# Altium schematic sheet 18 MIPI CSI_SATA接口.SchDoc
size 420 x 297 mm
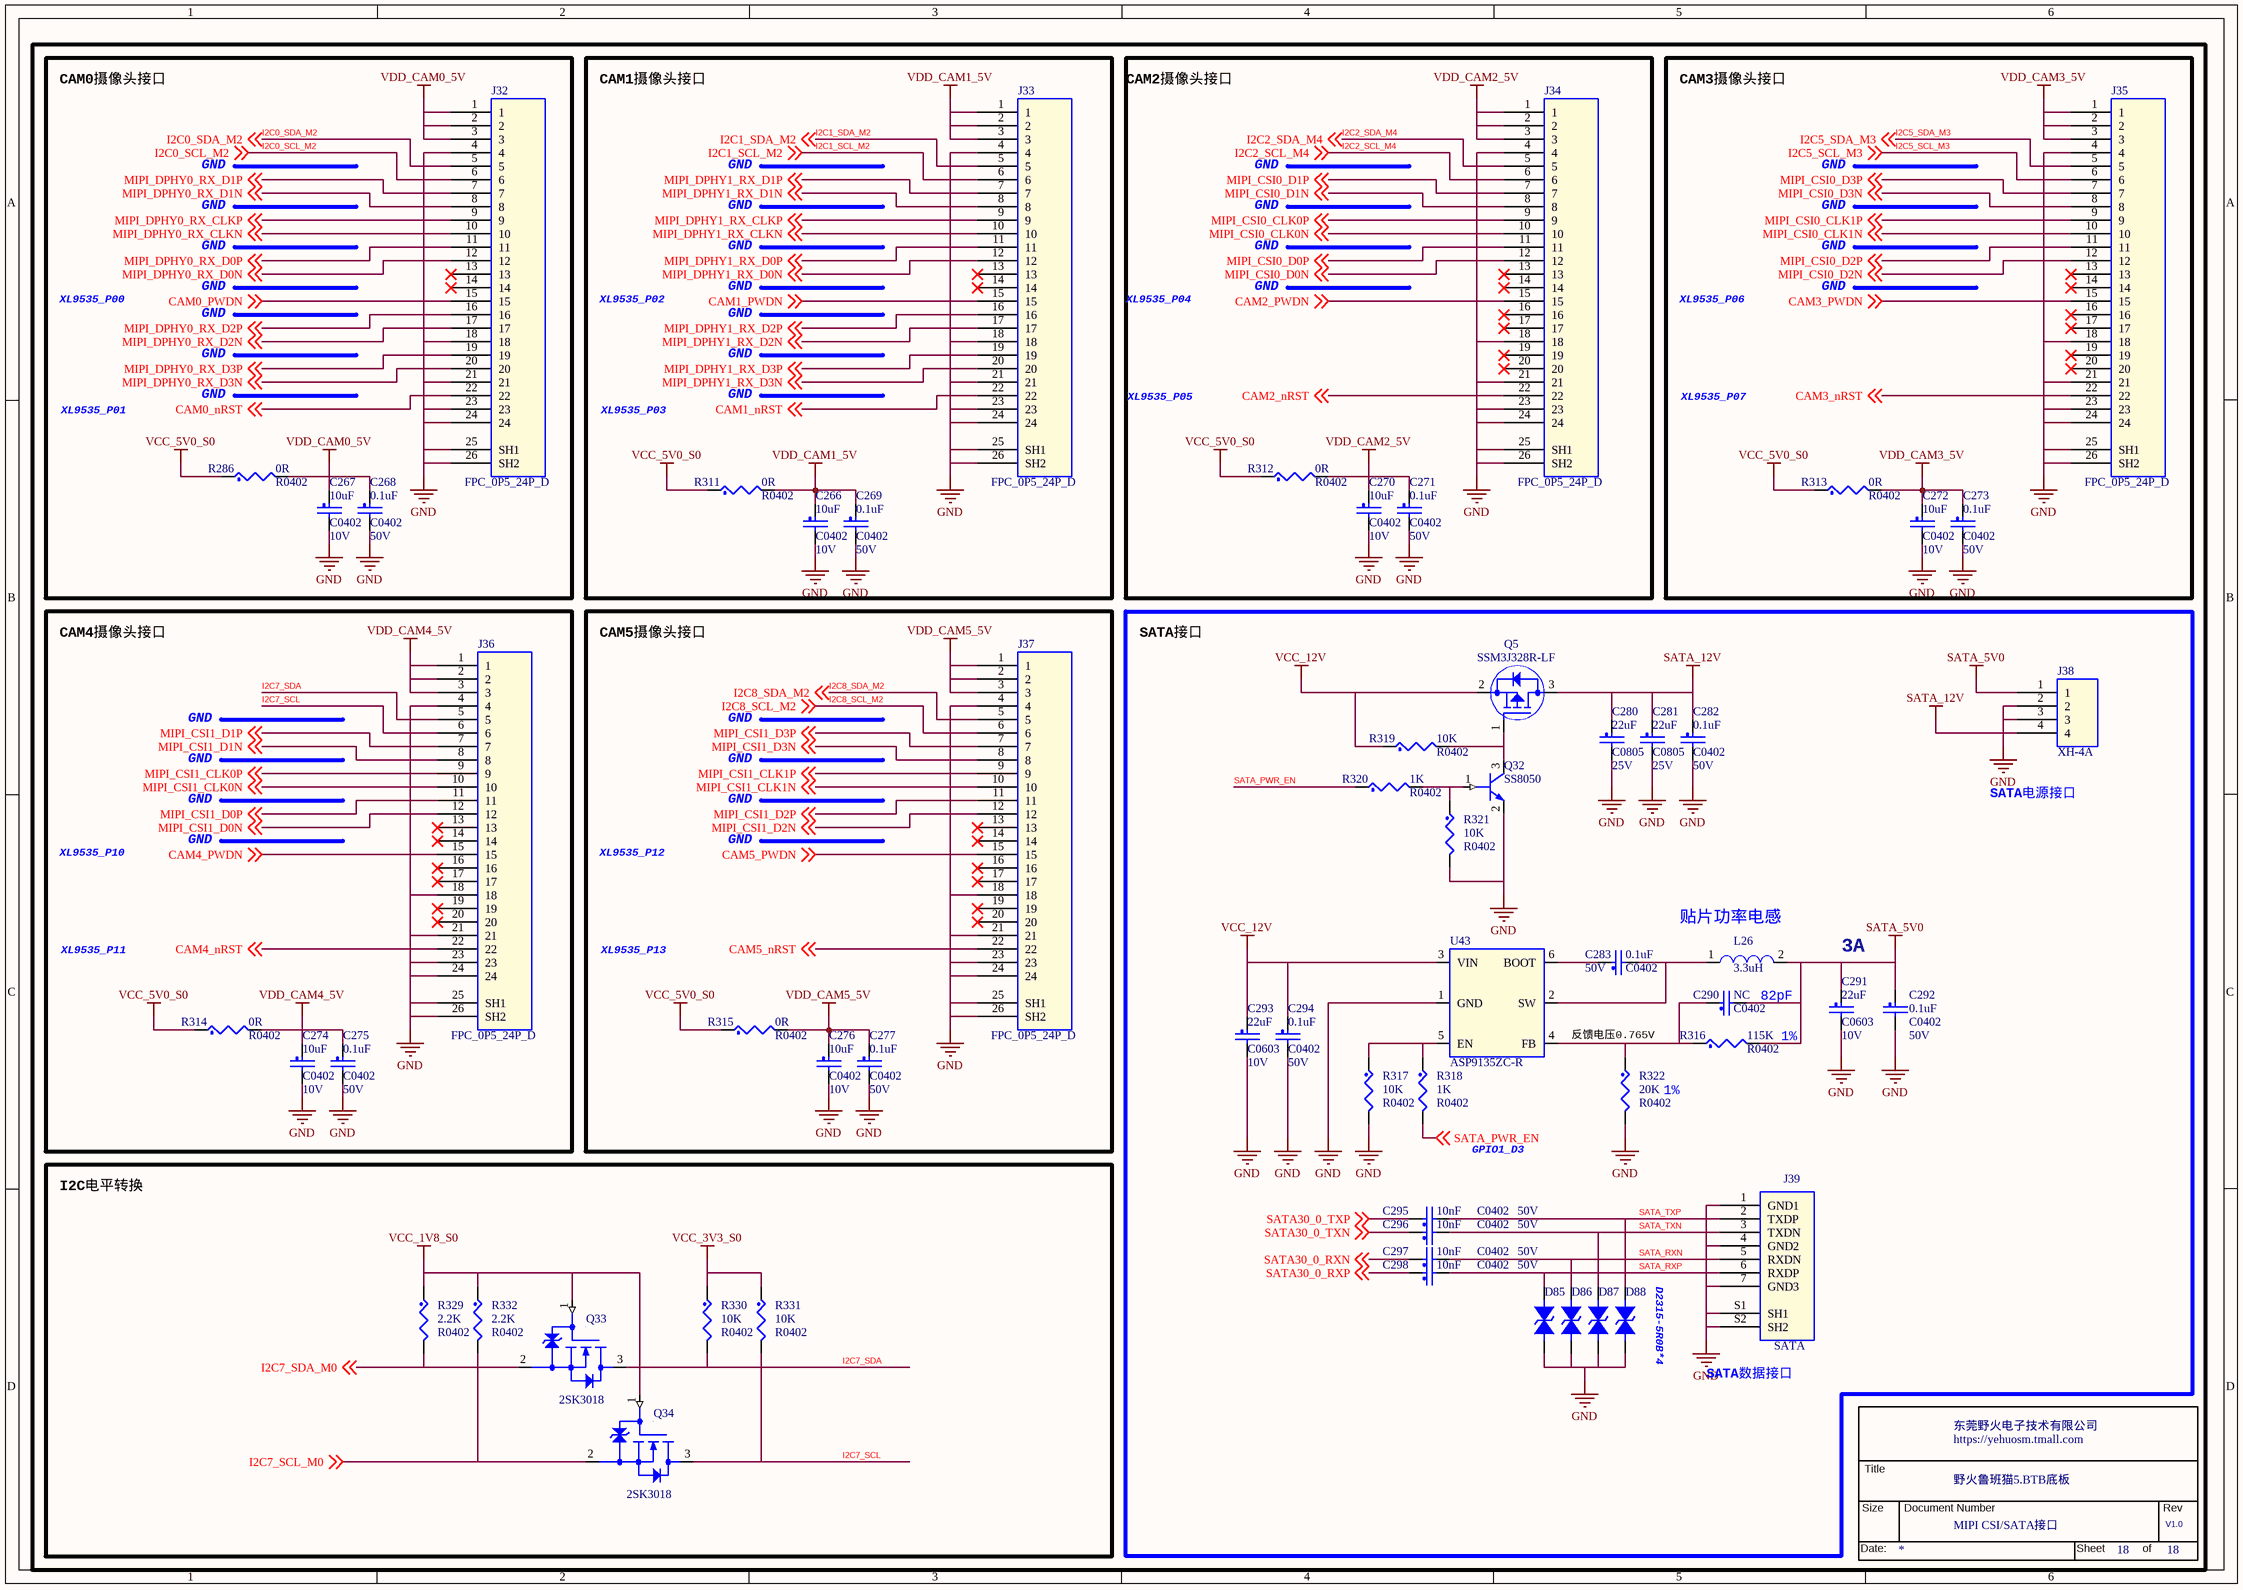
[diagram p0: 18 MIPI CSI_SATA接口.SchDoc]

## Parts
*  Doc: MIPI CSI/SATA接口  RevCode: V1.0  Title: 野火鲁班猫5.BTB底板  OrgName: 东莞野火电子技术有限公司  Page Number: 18  (hidden comment: TitleBlock_YHSCH)  (graphical)
C266  10uF  Voltage: 10V  [C0402]
C267  10uF  Voltage: 10V  [C0402]
C268  0.1uF  Voltage: 50V  [C0402]
C269  0.1uF  Voltage: 50V  [C0402]
C270  10uF  Voltage: 10V  [C0402]
C271  0.1uF  Voltage: 50V  [C0402]
C272  10uF  Voltage: 10V  [C0402]
C273  0.1uF  Voltage: 50V  [C0402]
C274  10uF  Voltage: 10V  [C0402]
C275  0.1uF  Voltage: 50V  [C0402]
C276  10uF  Voltage: 10V  [C0402]
C277  0.1uF  Voltage: 50V  [C0402]
C280  22uF  Voltage: 25V  [C0805]
C281  22uF  Voltage: 25V  [C0805]
C282  0.1uF  Voltage: 50V  [C0402]
C283  0.1uF  Voltage: 50V  [C0402]
C290  NC  [C0402]
C291  22uF  Voltage: 10V  [C0603]
C292  0.1uF  Voltage: 50V  [C0402]
C293  22uF  Voltage: 10V  [C0603]
C294  0.1uF  Voltage: 50V  [C0402]
C295  10nF  Voltage: 50V  [C0402]
C296  10nF  Voltage: 50V  [C0402]
C297  10nF  Voltage: 50V  [C0402]
C298  10nF  Voltage: 50V  [C0402]
D85  D2315-5R0B  [D0603/SMD]  (value not drawn)
D86  D2315-5R0B  [D0603/SMD]  (value not drawn)
D87  D2315-5R0B  [D0603/SMD]  (value not drawn)
D88  D2315-5R0B  [D0603/SMD]  (value not drawn)
J32  FPC_0P5_24P_D  [fpc_24p_0p5]
J33  FPC_0P5_24P_D  [fpc_24p_0p5]
J34  FPC_0P5_24P_D  [fpc_24p_0p5]
J35  FPC_0P5_24P_D  [fpc_24p_0p5]
J36  FPC_0P5_24P_D  [fpc_24p_0p5]
J37  FPC_0P5_24P_D  [fpc_24p_0p5]
J38  XH-4A  [XH2p54-4p]
J39  SATA  [ssata_v]
L26  3.3uH  [l4520]
Q5  SSM3J328R-LF  [SOT23]
Q32  SS8050  [SOT23]
Q33  2SK3018  [SOT23]
Q34  2SK3018  [SOT23]
R286  0R  [R0402]
R311  0R  [R0402]
R312  0R  [R0402]
R313  0R  [R0402]
R314  0R  [R0402]
R315  0R  [R0402]
R316  115K  [R0402]
R317  10K  [R0402]
R318  1K  [R0402]
R319  10K  [R0402]
R320  1K  [R0402]
R321  10K  [R0402]
R322  20K  [R0402]
R329  2.2K  [R0402]
R330  10K  [R0402]
R331  10K  [R0402]
R332  2.2K  [R0402]
U43  ASP9135ZC-R  [SOT23_6]

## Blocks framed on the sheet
CAM0摄像头接口: C267 C268 J32 R286
CAM1摄像头接口: C266 C269 J33 R311
CAM2摄像头接口: C270 C271 J34 R312
CAM3摄像头接口: C272 C273 J35 R313
CAM4摄像头接口: C274 C275 J36 R314
CAM5摄像头接口: C276 C277 J37 R315
3A: C280-C283 C290-C298 D85-D88 J38 J39 L26 Q5 Q32 R316-R322 U43
I2C电平转换: Q33 Q34 R329-R332

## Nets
GND: C266.2 C267.2 C268.2 C269.2 C270.2 C271.2 C272.2 C273.2 C274.2 C275.2 C276.2 C277.2 C280.2 C281.2 C282.2 C291.2 C292.2 C293.2 C294.2 D85.1 D86.1 D87.1 D88.1 J32.4 J32.18 J32.21 J32.23 J32.24 J32.25(SH1) J32.26(SH2) J33.4 J33.18 J33.21 J33.23 J33.24 J33.25(SH1) J33.26(SH2) J34.4 J34.18 J34.21 J34.23 J34.24 J34.25(SH1) J34.26(SH2) J35.4 J35.18 J35.21 J35.23 J35.24 J35.25(SH1) J35.26(SH2) J36.4 J36.18 J36.21 J36.23 J36.24 J36.25(SH1) J36.26(SH2) J37.4 J37.18 J37.21 J37.23 J37.24 J37.25(SH1) J37.26(SH2) J38.2 J38.3 J39.1(GND1) J39.4(GND2) J39.7(GND3) J39.S1(SH1) J39.S2(SH2) Q32.2(EMITTER) R317.2 R321.2 R322.2 U43.1(GND)
SATA_5V0: C290.2 C291.1 C292.1 J38.1 L26.2 R316.2
SATA_12V: C280.1 C281.1 C282.1 J38.4 Q5.3(DRAIN)
VCC_1V8_S0: Q33.1(GATE) Q34.1(GATE) R329.1 R332.1
VCC_3V3_S0: R330.1 R331.1
VCC_5V0_S0: R286.1 R311.1 R312.1 R313.1 R314.1 R315.1
VCC_12V: C293.1 C294.1 Q5.2(SOURCE) R319.1 U43.3(VIN)
VDD_CAM0_5V: C267.1 C268.1 J32.1 J32.2 J32.3 R286.2
VDD_CAM1_5V: C266.1 C269.1 J33.1 J33.2 J33.3 R311.2
VDD_CAM2_5V: C270.1 C271.1 J34.1 J34.2 J34.3 R312.2
VDD_CAM3_5V: C272.1 C273.1 J35.1 J35.2 J35.3 R313.2
VDD_CAM4_5V: C274.1 C275.1 J36.1 J36.2 J36.3 R314.2
VDD_CAM5_5V: C276.1 C277.1 J37.1 J37.2 J37.3 R315.2
CAM0_nRST: J32.22 ; off-sheet CAM0_nRST
CAM0_PWDN: J32.15 ; off-sheet CAM0_PWDN
CAM1_nRST: J33.22 ; off-sheet CAM1_nRST
CAM1_PWDN: J33.15 ; off-sheet CAM1_PWDN
CAM2_nRST: J34.22 ; off-sheet CAM2_nRST
CAM2_PWDN: J34.15 ; off-sheet CAM2_PWDN
CAM3_nRST: J35.22 ; off-sheet CAM3_nRST
CAM3_PWDN: J35.15 ; off-sheet CAM3_PWDN
CAM4_nRST: J36.22 ; off-sheet CAM4_nRST
CAM4_PWDN: J36.15 ; off-sheet CAM4_PWDN
CAM5_nRST: J37.22 ; off-sheet CAM5_nRST
CAM5_PWDN: J37.15 ; off-sheet CAM5_PWDN
I2C0_SCL_M2: J32.6 ; off-sheet I2C0_SCL_M2
I2C0_SDA_M2: J32.5 ; off-sheet I2C0_SDA_M2
I2C1_SCL_M2: J33.6 ; off-sheet I2C1_SCL_M2
I2C1_SDA_M2: J33.5 ; off-sheet I2C1_SDA_M2
I2C2_SCL_M4: J34.6 ; off-sheet I2C2_SCL_M4
I2C2_SDA_M4: J34.5 ; off-sheet I2C2_SDA_M4
I2C5_SCL_M3: J35.6 ; off-sheet I2C5_SCL_M3
I2C5_SDA_M3: J35.5 ; off-sheet I2C5_SDA_M3
I2C7_SCL: J36.6 Q34.3(DRAIN) R331.2
I2C7_SCL_M0: Q34.2(SOURCE) R332.2 ; off-sheet I2C7_SCL_M0
I2C7_SDA: J36.5 Q33.3(DRAIN) R330.2
I2C7_SDA_M0: Q33.2(SOURCE) R329.2 ; off-sheet I2C7_SDA_M0
I2C8_SCL_M2: J37.6 ; off-sheet I2C8_SCL_M2
I2C8_SDA_M2: J37.5 ; off-sheet I2C8_SDA_M2
MIPI_CSI0_CLK0N: J34.10 ; off-sheet MIPI_CSI0_CLK0N
MIPI_CSI0_CLK0P: J34.9 ; off-sheet MIPI_CSI0_CLK0P
MIPI_CSI0_CLK1N: J35.10 ; off-sheet MIPI_CSI0_CLK1N
MIPI_CSI0_CLK1P: J35.9 ; off-sheet MIPI_CSI0_CLK1P
MIPI_CSI0_D0N: J34.12 ; off-sheet MIPI_CSI0_D0N
MIPI_CSI0_D0P: J34.11 ; off-sheet MIPI_CSI0_D0P
MIPI_CSI0_D1N: J34.8 ; off-sheet MIPI_CSI0_D1N
MIPI_CSI0_D1P: J34.7 ; off-sheet MIPI_CSI0_D1P
MIPI_CSI0_D2N: J35.12 ; off-sheet MIPI_CSI0_D2N
MIPI_CSI0_D2P: J35.11 ; off-sheet MIPI_CSI0_D2P
MIPI_CSI0_D3N: J35.8 ; off-sheet MIPI_CSI0_D3N
MIPI_CSI0_D3P: J35.7 ; off-sheet MIPI_CSI0_D3P
MIPI_CSI1_CLK0N: J36.10 ; off-sheet MIPI_CSI1_CLK0N
MIPI_CSI1_CLK0P: J36.9 ; off-sheet MIPI_CSI1_CLK0P
MIPI_CSI1_CLK1N: J37.10 ; off-sheet MIPI_CSI1_CLK1N
MIPI_CSI1_CLK1P: J37.9 ; off-sheet MIPI_CSI1_CLK1P
MIPI_CSI1_D0N: J36.12 ; off-sheet MIPI_CSI1_D0N
MIPI_CSI1_D0P: J36.11 ; off-sheet MIPI_CSI1_D0P
MIPI_CSI1_D1N: J36.8 ; off-sheet MIPI_CSI1_D1N
MIPI_CSI1_D1P: J36.7 ; off-sheet MIPI_CSI1_D1P
MIPI_CSI1_D2N: J37.12 ; off-sheet MIPI_CSI1_D2N
MIPI_CSI1_D2P: J37.11 ; off-sheet MIPI_CSI1_D2P
MIPI_CSI1_D3N: J37.8 ; off-sheet MIPI_CSI1_D3N
MIPI_CSI1_D3P: J37.7 ; off-sheet MIPI_CSI1_D3P
MIPI_DPHY0_RX_CLKN: J32.10 ; off-sheet MIPI_DPHY0_RX_CLKN
MIPI_DPHY0_RX_CLKP: J32.9 ; off-sheet MIPI_DPHY0_RX_CLKP
MIPI_DPHY0_RX_D0N: J32.12 ; off-sheet MIPI_DPHY0_RX_D0N
MIPI_DPHY0_RX_D0P: J32.11 ; off-sheet MIPI_DPHY0_RX_D0P
MIPI_DPHY0_RX_D1N: J32.8 ; off-sheet MIPI_DPHY0_RX_D1N
MIPI_DPHY0_RX_D1P: J32.7 ; off-sheet MIPI_DPHY0_RX_D1P
MIPI_DPHY0_RX_D2N: J32.17 ; off-sheet MIPI_DPHY0_RX_D2N
MIPI_DPHY0_RX_D2P: J32.16 ; off-sheet MIPI_DPHY0_RX_D2P
MIPI_DPHY0_RX_D3N: J32.20 ; off-sheet MIPI_DPHY0_RX_D3N
MIPI_DPHY0_RX_D3P: J32.19 ; off-sheet MIPI_DPHY0_RX_D3P
MIPI_DPHY1_RX_CLKN: J33.10 ; off-sheet MIPI_DPHY1_RX_CLKN
MIPI_DPHY1_RX_CLKP: J33.9 ; off-sheet MIPI_DPHY1_RX_CLKP
MIPI_DPHY1_RX_D0N: J33.12 ; off-sheet MIPI_DPHY1_RX_D0N
MIPI_DPHY1_RX_D0P: J33.11 ; off-sheet MIPI_DPHY1_RX_D0P
MIPI_DPHY1_RX_D1N: J33.8 ; off-sheet MIPI_DPHY1_RX_D1N
MIPI_DPHY1_RX_D1P: J33.7 ; off-sheet MIPI_DPHY1_RX_D1P
MIPI_DPHY1_RX_D2N: J33.17 ; off-sheet MIPI_DPHY1_RX_D2N
MIPI_DPHY1_RX_D2P: J33.16 ; off-sheet MIPI_DPHY1_RX_D2P
MIPI_DPHY1_RX_D3N: J33.20 ; off-sheet MIPI_DPHY1_RX_D3N
MIPI_DPHY1_RX_D3P: J33.19 ; off-sheet MIPI_DPHY1_RX_D3P
SATA30_0_RXN: C297.1 ; off-sheet SATA30_0_RXN
SATA30_0_RXP: C298.1 ; off-sheet SATA30_0_RXP
SATA30_0_TXN: C296.1 ; off-sheet SATA30_0_TXN
SATA30_0_TXP: C295.1 ; off-sheet SATA30_0_TXP
SATA_PWR_EN: R318.2 R320.1 ; off-sheet SATA_PWR_EN
SATA_RXN: C297.2 D86.2 J39.5(RXDN)
SATA_RXP: C298.2 D85.2 J39.6(RXDP)
SATA_TXN: C296.2 D87.2 J39.3(TXDN)
SATA_TXP: C295.2 D88.2 J39.2(TXDP)
NetC283_1: C283.1 U43.6(BOOT)
NetC283_2: C283.2 L26.1 U43.2(SW)
NetC290_1: C290.1 R316.1 R322.1 U43.4(FB)
NetQ5_1: Q5.1(GATE) Q32.3(COLLECTOR) R319.2
NetQ32_1: Q32.1(BASE) R320.2 R321.1
NetR317_1: R317.1 R318.1 U43.5(EN)

Not connected (* = marked no-connect by the designer): J32 13* 14*; J33 13* 14*; J34 13* 14* 16* 17* 19* 20*; J35 13* 14* 16* 17* 19* 20*; J36 13* 14* 16* 17* 19* 20*; J37 13* 14* 16* 17* 19* 20*

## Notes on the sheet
- GND
- XL9535_P00
- XL9535_P02
- XL9535_P04
- XL9535_P06
- XL9535_P01
- XL9535_P03
- XL9535_P05
- XL9535_P07
- SATA接口
- SATA电源接口
- XL9535_P10
- XL9535_P12
- (near L26) 贴片功率电感
- XL9535_P11
- XL9535_P13
- 82pF
- 反馈电压0.765V
- 1%
- GPIO1_D3
- (near D88) D2315-5R0B*4
- (near J39) SATA数据接口

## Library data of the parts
* = TitleBlock_YHSCH: Cage Code: 1
C266 C267 = CAP_NP: CLASS: DISCRETE; 规格: 贴片电容10uF 20% 10V X5R 0402; 规格编号: CL05A106MP8NUB8; 条码: EBF29060247; 品牌: 三星; 类别: 贴片电容0402; 规格书: 三星电容.pdf; 价格: 0.518415; 生命周期: 量产
C268 C269 C282 C283 = CAP_NP: CLASS: DISCRETE; 生命周期: 量产; 价格: 0.029826; 规格书: 风华电容.pdf; 类别: 贴片电容0402; 品牌: 风华; 条码: EBF29060118; 规格编号: 0402X104K500NT; 规格: 贴片电容0.1uF 10% 50V X5R 0402
C270 C272 C274 C276 = CAP_NP: CLASS: DISCRETE; 生命周期: 量产; 价格: 0.518415; 规格书: 三星电容.pdf; 类别: 贴片电容0402; 品牌: 三星; 条码: EBF29060247; 规格编号: CL05A106MP8NUB8; 规格: 贴片电容10uF 20% 10V X5R 0402
C271 C273 C275 C277 C292 C294 = CAP_NP: CLASS: DISCRETE; 规格: 贴片电容0.1uF 10% 50V X5R 0402; 规格编号: 0402X104K500NT; 条码: EBF29060118; 品牌: 风华; 类别: 贴片电容0402; 规格书: 风华电容.pdf; 价格: 0.029826; 生命周期: 量产
C280 C281 = CAP_NP: CLASS: DISCRETE; 规格: 贴片电容22uF 20% 25V X5R 0805; 规格编号: 0805X226M250NT; 条码: EBF29060173; 品牌: 风华; 类别: 贴片电容0805; 规格书: 风华电容.pdf; 价格: 0.285631; 生命周期: 量产
C290 = CAP_NP: CLASS: DISCRETE; 规格: 贴片电容NC 预留; 条码: EBF29060149; 类别: 贴片电容0402
C291 C293 = CAP_NP: CLASS: DISCRETE; 生命周期: 量产; 价格: 0.078818; 规格书: 三星电容.pdf; 类别: 贴片电容0603; 品牌: 三星; 条码: EBF29060163; 规格编号: CL10A226MP8NUNE; 规格: 贴片电容22uF 20% 10V X5R 0603
C295-C298 = CAP_NP: CLASS: DISCRETE; 规格: 贴片电容10nF 10% 50V X7R 0402; 规格编号: CC0402KRX7R9BB103; 条码: EBF29060245; 品牌: 国巨; 类别: 贴片电容0402; 规格书: 国巨-贴片电容.pdf; 价格: 0.003808; 生命周期: 量产
D85-D88 = DIODE BI-DIR TRIG: PCB Footprint: esd0402; 备注: 通用; 生命周期: 量产; 规格书: 千虹_D2315-5R0B.pdf; 类别: 贴片ESD; 品牌: 千虹; 条码: EBFCIS240517170922; 规格: 防静电保护ESD二极管 反向工作电压5V 击穿电压7V 钳位电压10.5V 结电容Cj 0.3pF
J32-J36 = FPC-24P: 规格: FPC连接器 针脚数24 间距0.5mmm 下接 卧贴 翻盖式; 规格编号: AFC01-S24FCA-00; 条码: EBF29040059; 品牌: 钜硕电子; 类别: FPC连接器; 规格书: 钜硕电子-FPC间距0.5mm.pdf; 价格: 0.368739; 生命周期: 量产
J37 = FPC-24P: 可替代料: EBF29040059; 生命周期: 量产; 价格: 0.368739; 规格书: 钜硕电子-FPC间距0.5mm.pdf; 类别: FPC连接器; 品牌: 钜硕电子; 规格编号: AFC01-S24FCA-00; 规格: FPC连接器 针脚数24 间距0.5mmm 下接 卧贴 翻盖式
J38 = 1X4PIN: 可替代料: EBF29040012; 生命周期: 量产; 价格: 0.041116; 规格书: 博穆精密-XH2.54.pdf; 类别: XH连接器; 品牌: 博穆精密; 规格: 直针XH2.54-4P 间距2.54MM 拔插式 接插件 直插
J39 = SATA: 生命周期: 量产; 规格书: SATA_7PIN.pdf; 类别: SATA连接器; 品牌: 华宇创; 条码: EBF29040076; 规格编号: HYCW01-SATA07-205B; 规格: SATA 7PIN 全包开窗 A型
L26 = IND: CLASS: DISCRETE; 规格: 贴片电感3.3uH ±20% 3A 直流电阻69mΩ; 条码: EBF29050040; 品牌: 台庆; 类别: 贴片电感0402; 规格书: 台庆-功率电感.pdf; 生命周期: 量产; 规格编号: TMPC0402HP-3R3MG-Z02; 价格: 1.5992
Q5 = MOSFET_P: CLASS: IC; 丝印: KFH-XXX; 生命周期: 量产; 价格: 0.447836; 规格书: SSM3J328R-LF.pdf; 类别: P-MOS; 品牌: 东芝; 条码: EBF29280008; 规格编号: SSM3J328R LF; 规格: P沟道MOS 导通电阻29.8mΩ 电流3A 1.5V可驱动
Q32 = NPN: CLASS: IC; 丝印: Y1; 生命周期: 量产; 价格: 0.086744; 规格书: 江苏长电-SS8050Y1.pdf; 类别: 贴片三极管SOT-23; 品牌: 江苏长电; 条码: EBF29090001; 规格: 贴片三极管SS8050 集电极电流1.5A 额定功率300mW NPN
Q33 = 2SK3018: CLASS: IC; 丝印: KN; 生命周期: 量产; 价格: 0.120725; 规格书: 长电科技-2SK3018.pdf; 类别: N-MOS; 品牌: 江苏长电; 条码: EBF29280009; 规格: N沟道MOS 导通电阻8Ω 电流10mA 0.8V可驱动
Q34 = 2SK3018: CLASS: IC; 规格: N沟道MOS 导通电阻8Ω 电流10mA 0.8V可驱动; 条码: EBF29280009; 品牌: 江苏长电; 类别: N-MOS; 规格书: 长电科技-2SK3018.pdf; 价格: 0.120725; 生命周期: 量产; 丝印: KN
R286 R311 = RES: CLASS: DISCRETE; 生命周期: 量产; 规格书: 合科泰-RI系列电阻.pdf; 类别: 贴片电阻0402; 品牌: 合科泰; 条码: EBF29070049; 规格编号: RI0402L000FT; 规格: 贴片电阻0R 1% 1/16W 0402
R312-R315 = RES: CLASS: DISCRETE; 规格: 贴片电阻0R 1% 1/16W 0402; 规格编号: RI0402L000FT; 条码: EBF29070049; 品牌: 合科泰; 类别: 贴片电阻0402; 规格书: 合科泰-RI系列电阻.pdf; 生命周期: 量产
R316 = RES: CLASS: DISCRETE; 规格: 贴片电阻115K 1% 1/16W 0402; 规格编号: AC0402FR-07115KL; 条码: EBF29070290; 品牌: 国巨; 类别: 贴片电阻0402; 规格书: YAGEO国巨厚膜无铅电阻.pdf; 价格: 0.006087; 生命周期: 量产
R317 R321 = RES: CLASS: DISCRETE; 生命周期: 量产; 价格: 0.002773; 规格书: 厚声-无铅厚膜电阻.pdf; 类别: 贴片电阻0402; 品牌: 厚声; 条码: EBF29070046; 规格编号: 0402WGF1002TCE; 规格: 贴片电阻10K 1% 1/16W 0402
R318 R320 = RES: CLASS: DISCRETE; 规格: 贴片电阻1K 1% 1/16W 0402; 规格编号: RI0402L1001FT; 条码: EBF29070050; 品牌: 合科泰; 类别: 贴片电阻0402; 规格书: 合科泰-RI系列电阻.pdf; 生命周期: 量产
R319 = RES: CLASS: DISCRETE; 规格: 贴片电阻10K 1% 1/16W 0402; 规格编号: 0402WGF1002TCE; 条码: EBF29070046; 品牌: 厚声; 类别: 贴片电阻0402; 规格书: 厚声-无铅厚膜电阻.pdf; 价格: 0.002773; 生命周期: 量产
R322 = RES: CLASS: DISCRETE; 规格: 贴片电阻20K 1% 1/16W 0402; 规格编号: 0402WGF2002TCE; 条码: EBF29070223; 品牌: 厚声; 类别: 贴片电阻0402; 规格书: 厚声-无铅厚膜电阻.pdf; 价格: 0.002473; 生命周期: 量产
R329 R332 = RES: CLASS: DISCRETE; 生命周期: 量产; 规格书: 合科泰-RI系列电阻.pdf; 类别: 贴片电阻0402; 品牌: 合科泰; 条码: EBF29070051; 规格编号: RI0402L2201FT; 规格: 贴片电阻2.2K 1% 1/16W 0402
R330 R331 = RES: CLASS: DISCRETE; 生命周期: 量产; 规格书: 厚声-无铅厚膜电阻.pdf; 类别: 贴片电阻0402; 品牌: 厚声; 条码: EBF29070046; 规格编号: 0402WGF1002TCE; 规格: 贴片电阻10K 1% 1/16W 0402; 价格: 0.002773
U43 = TP6327GS6: 生命周期: 量产; 规格书: 安森德_ASP9135ZC-R.pdf; 类别: 电源管理-DCDC; 品牌: 安森德; 条码: EBFCIS240710113940; 规格: DC-DC电源芯片 可输出电流 3A 开关工作频率 600kHz 输出类型 ADJ 输入电压范围：4V-18V; 备注: RK3566金手指与BTB底板替换物料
